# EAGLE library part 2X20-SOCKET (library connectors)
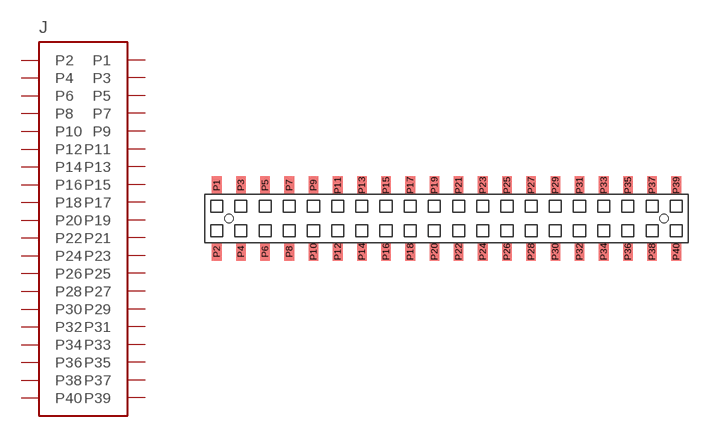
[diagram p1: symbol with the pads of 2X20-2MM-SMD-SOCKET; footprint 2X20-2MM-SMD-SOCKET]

Designator prefix J

## 2X20-SOCKET2MM  [2X20-2MM-SMD-SOCKET]
P1  P1  pas
P2  P2  pas
P3  P3  pas
P4  P4  pas
P5  P5  pas
P6  P6  pas
P7  P7  pas
P8  P8  pas
P9  P9  pas
P10  P10  pas
P11  P11  pas
P12  P12  pas
P13  P13  pas
P14  P14  pas
P15  P15  pas
P16  P16  pas
P17  P17  pas
P18  P18  pas
P19  P19  pas
P20  P20  pas
P21  P21  pas
P22  P22  pas
P23  P23  pas
P24  P24  pas
P25  P25  pas
P26  P26  pas
P27  P27  pas
P28  P28  pas
P29  P29  pas
P30  P30  pas
P31  P31  pas
P32  P32  pas
P33  P33  pas
P34  P34  pas
P35  P35  pas
P36  P36  pas
P37  P37  pas
P38  P38  pas
P39  P39  pas
P40  P40  pas

## Footprint 2X20-2MM-SMD-SOCKET (pad centres in mm)
smd 0.8 x 1.5: P1 -19,2.75; P2 -19,-2.75; P3 -17,2.75; P4 -17,-2.75; P5 -15,2.75; P6 -15,-2.75; P7 -13,2.75; P8 -13,-2.75; P9 -11,2.75; P10 -11,-2.75; P11 -9,2.75; P12 -9,-2.75; P13 -7,2.75; P14 -7,-2.75; P15 -5,2.75; P16 -5,-2.75; P17 -3,2.75; P18 -3,-2.75; P19 -1,2.75; P20 -1,-2.75; P21 1,2.75; P22 1,-2.75; P23 3,2.75; P24 3,-2.75; P25 5,2.75; P26 5,-2.75; P27 7,2.75; P28 7,-2.75; P29 9,2.75; P30 9,-2.75; P31 11,2.75; P32 11,-2.75; P33 13,2.75; P34 13,-2.75; P35 15,2.75; P36 15,-2.75; P37 17,2.75; P38 17,-2.75; P39 19,2.75; P40 19,-2.75
hole 0.7 at -18,0
hole 0.7 at 18,0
